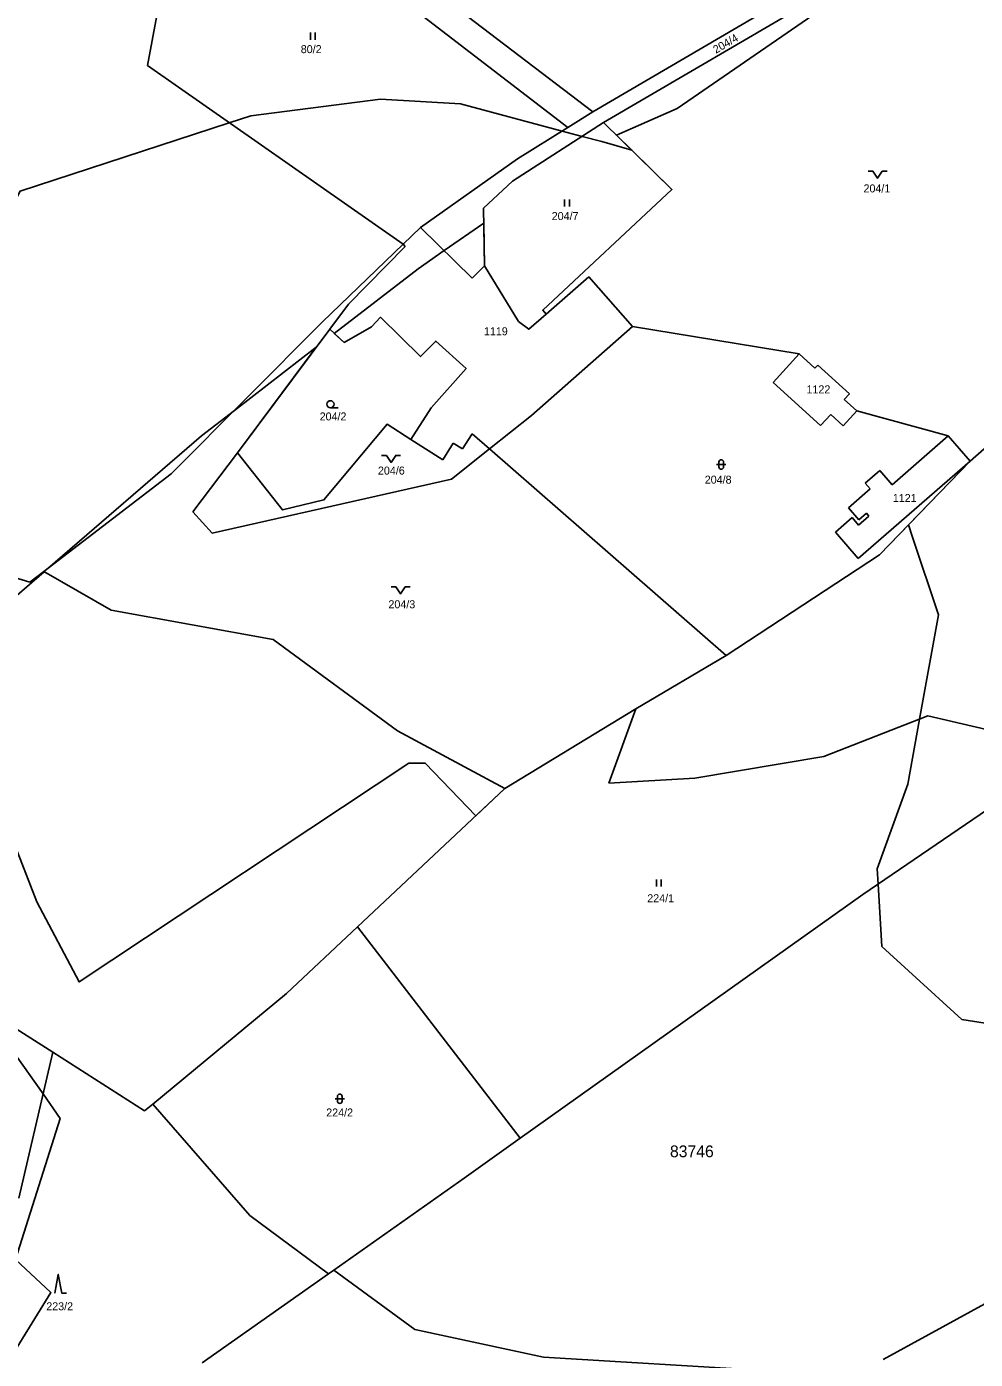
# Model space of a CAD drawing. Extents: x -547623 to -538651, y -1096714 to -1086522.
# Drawn here: x -542226.1 to -542024.7, y -1091898.7 to -1091615.6 of the extents above; entities that cross this region are included whole.
import ezdxf

# ---------------------------------------------------------------- set-up
doc = ezdxf.new("R2010")
doc.units = 0
for name, color, linetype in [('Vrstva 1', 7, 'Continuous'), ('Vrstva 25', 7, 'Continuous'), ('Vrstva 52', 7, 'Continuous'), ('Vrstva 53', 7, 'Continuous'), ('Vrstva 86', 7, 'Continuous')]:
    doc.layers.add(name, color=color, linetype=linetype)

msp = doc.modelspace()

# ---------------------------------------------------------------- linework, layer by layer
at = {"layer": 'Vrstva 1'}
for points in [[(-542232.34, -1091537.35), (-542105.9, -1091633.69)], [(-542111.2, -1091637), (-542220.74, -1091552.82)], [(-542195.28, -1091596.05), (-542200.48, -1091623.86)], [(-542105.9, -1091633.69), (-542059.17, -1091606.26)], [(-542103.64, -1091635.97), (-542056.84, -1091608.54)], [(-542200.48, -1091623.86), (-542146.2, -1091661.82)], [(-542122.95, -1091648.39), (-542103.64, -1091635.97)], [(-542111.2, -1091637), (-542105.9, -1091633.69)], [(-542103.64, -1091635.97), (-542089.09, -1091650.19)], [(-542121.88, -1091643.68), (-542111.2, -1091637)], [(-542142.48, -1091658.23), (-542121.88, -1091643.68)], [(-542122.95, -1091648.39), (-542129.11, -1091654.13)], [(-542089.09, -1091650.19), (-542116.54, -1091675.79)], [(-542129.11, -1091654.13), (-542128.92, -1091666.36)], [(-542146.2, -1091661.82), (-542142.48, -1091658.23)], [(-542142.48, -1091658.23), (-542131.51, -1091669)], [(-542163.32, -1091678.3), (-542146.2, -1091661.82)], [(-542146.2, -1091661.82), (-542145.73, -1091662.28)], [(-542157.78, -1091674.55), (-542145.73, -1091662.28)], [(-542128.92, -1091666.36), (-542131.51, -1091669)], [(-542128.92, -1091666.36), (-542121.67, -1091678.18)], [(-542115.79, -1091676.64), (-542106.74, -1091668.71)], [(-542106.74, -1091668.71), (-542097.45, -1091679.3)], [(-542161.77, -1091679.87), (-542157.78, -1091674.55)], [(-542116.54, -1091675.79), (-542115.79, -1091676.64)], [(-542195.42, -1091710.59), (-542163.32, -1091678.3)], [(-542150.97, -1091677.32), (-542152.93, -1091679.32)], [(-542150.97, -1091677.32), (-542142.48, -1091685.66)], [(-542121.67, -1091678.18), (-542119.46, -1091679.86)], [(-542119.46, -1091679.86), (-542115.79, -1091676.64)], [(-542181.4, -1091706.09), (-542161.77, -1091679.87)], [(-542158.71, -1091682.65), (-542161.77, -1091679.87)], [(-542152.93, -1091679.32), (-542158.71, -1091682.65)], [(-542097.45, -1091679.3), (-542118.96, -1091698.16)], [(-542097.45, -1091679.3), (-542062.05, -1091685.09)], [(-541994.45, -1091680.31), (-542025.78, -1091707.87)], [(-542142.48, -1091685.66), (-542139.25, -1091682.37)], [(-542139.25, -1091682.37), (-542132.81, -1091688.18)], [(-542067.58, -1091691.14), (-542062.05, -1091685.09)], [(-542062.05, -1091685.09), (-542058.73, -1091688.13)], [(-542132.81, -1091688.18), (-542140.22, -1091696.53)], [(-542058.73, -1091688.13), (-542058.12, -1091687.46)], [(-542058.12, -1091687.46), (-542051.41, -1091693.61)], [(-542057.55, -1091700.32), (-542067.58, -1091691.14)], [(-542052.49, -1091694.79), (-542051.41, -1091693.61)], [(-542052.49, -1091694.79), (-542049.83, -1091697.22)], [(-542140.22, -1091696.53), (-542144.53, -1091703.27)], [(-542118.96, -1091698.16), (-542127.87, -1091705.29)], [(-542057.55, -1091700.32), (-542055.39, -1091697.96)], [(-542052.73, -1091700.39), (-542055.39, -1091697.96)], [(-542052.73, -1091700.39), (-542049.83, -1091697.22)], [(-542049.83, -1091697.22), (-542030.44, -1091702.52)], [(-542163.03, -1091716.13), (-542149.59, -1091700.04)], [(-542149.59, -1091700.04), (-542144.53, -1091703.27)], [(-542137.79, -1091707.58), (-542144.53, -1091703.27)], [(-542137.79, -1091707.58), (-542135.53, -1091704.04)], [(-542135.53, -1091704.04), (-542133.59, -1091705.28)], [(-542133.59, -1091705.28), (-542131.54, -1091702.08)], [(-542131.54, -1091702.08), (-542127.87, -1091705.29)], [(-542030.44, -1091702.52), (-542042.35, -1091712.89)], [(-542030.44, -1091702.52), (-542025.78, -1091707.87)], [(-542190.82, -1091718.67), (-542181.4, -1091706.09)], [(-542181.4, -1091706.09), (-542171.82, -1091718.24)], [(-542127.87, -1091705.29), (-542135.92, -1091711.73)], [(-542127.87, -1091705.29), (-542077.6, -1091749.14)], [(-542025.78, -1091707.87), (-542049.53, -1091728.55)], [(-542044.98, -1091709.87), (-542048.07, -1091712.56)], [(-542045, -1091727.75), (-542025.78, -1091707.87)], [(-542044.98, -1091709.87), (-542042.35, -1091712.89)], [(-542222.5, -1091731.35), (-542195.42, -1091710.59)], [(-542186.74, -1091723.15), (-542135.92, -1091711.73)], [(-542048.07, -1091712.56), (-542047.02, -1091713.77)], [(-542288.55, -1091714.43), (-542225.46, -1091733.62)], [(-542047.02, -1091713.77), (-542051.62, -1091717.77)], [(-542171.82, -1091718.24), (-542163.03, -1091716.13)], [(-542051.62, -1091717.77), (-542049.39, -1091720.34)], [(-542190.82, -1091718.67), (-542186.74, -1091723.15)], [(-542054.39, -1091722.97), (-542050.84, -1091719.88)], [(-542050.84, -1091719.88), (-542049.47, -1091721.47)], [(-542047.28, -1091719.56), (-542049.47, -1091721.47)], [(-542049.39, -1091720.34), (-542047.8, -1091718.96)], [(-542047.8, -1091718.96), (-542047.28, -1091719.56)], [(-542054.39, -1091722.97), (-542049.53, -1091728.55)], [(-542077.6, -1091749.14), (-542045, -1091727.75)], [(-542225.46, -1091733.62), (-542222.5, -1091731.35)], [(-542208.21, -1091739.5), (-542222.5, -1091731.35)], [(-542173.78, -1091745.78), (-542208.21, -1091739.5)], [(-542147.38, -1091765.19), (-542173.78, -1091745.78)], [(-542096.79, -1091760.5), (-542077.6, -1091749.14)], [(-542124.62, -1091777.44), (-542096.79, -1091760.5)], [(-542102.47, -1091776.26), (-542096.79, -1091760.5)], [(-542034.72, -1091761.97), (-542056.84, -1091770.59)], [(-542022.29, -1091764.85), (-542034.72, -1091761.97)], [(-542124.62, -1091777.44), (-542147.38, -1091765.19)], [(-542056.84, -1091770.59), (-542084.27, -1091775.22)], [(-542048.58, -1091799.95), (-542011.16, -1091774.42)], [(-542155.9, -1091806.83), (-542124.62, -1091777.44)], [(-542084.27, -1091775.22), (-542102.47, -1091776.26)], [(-542121.31, -1091851.72), (-542048.58, -1091799.95)], [(-542170.95, -1091820.98), (-542155.9, -1091806.83)], [(-542155.9, -1091806.83), (-542121.31, -1091851.72)], [(-542199.38, -1091844.47), (-542170.95, -1091820.98)], [(-542229.17, -1091827.94), (-542220.59, -1091833.44)], [(-542227.83, -1091864.42), (-542220.59, -1091833.44)], [(-542220.59, -1091833.44), (-542201.13, -1091845.92)], [(-542201.13, -1091845.92), (-542199.38, -1091844.47)], [(-542199.38, -1091844.47), (-542178.75, -1091868.1)], [(-542133.23, -1091860.2), (-542121.31, -1091851.72)], [(-542160.92, -1091879.72), (-542133.23, -1091860.2)], [(-542044.21, -1091898.74), (-541981.66, -1091864.43)], [(-542178.75, -1091868.1), (-542162.04, -1091880.51)], [(-542162.04, -1091880.51), (-542160.92, -1091879.72)], [(-542160.92, -1091879.72), (-542143.69, -1091892.32)], [(-542188.88, -1091899.43), (-542162.04, -1091880.51)], [(-542143.69, -1091892.32), (-542116.39, -1091898.18)], [(-542116.39, -1091898.18), (-542069.46, -1091901.06)]]:
    msp.add_lwpolyline(points, dxfattribs=at)
at = {"layer": 'Vrstva 25'}
for p, q in [((-542165.89, -1091618.35), (-542165.89, -1091616.85)), ((-542164.89, -1091618.35), (-542164.89, -1091616.85)), ((-542111.89, -1091653.77), (-542111.89, -1091652.27)), ((-542110.89, -1091653.77), (-542110.89, -1091652.27)), ((-542161.62, -1091696.53), (-542160.02, -1091696.53)), ((-542079.62, -1091708.59), (-542077.62, -1091708.59)), ((-542079.12, -1091709.09), (-542079.12, -1091708.09)), ((-542078.12, -1091708.09), (-542078.12, -1091709.09)), ((-542092.4, -1091798.24), (-542092.4, -1091796.74)), ((-542091.4, -1091798.24), (-542091.4, -1091796.74)), ((-542160.15, -1091843.82), (-542160.15, -1091842.82)), ((-542159.15, -1091842.82), (-542159.15, -1091843.82)), ((-542160.65, -1091843.32), (-542158.65, -1091843.32))]:
    msp.add_line(p, q, dxfattribs=at)
for points in [[(-542047.42, -1091646.28), (-542046.42, -1091646.28), (-542045.42, -1091647.78), (-542044.42, -1091646.28), (-542043.42, -1091646.28)], [(-542150.75, -1091706.66), (-542149.75, -1091706.66), (-542148.75, -1091708.16), (-542147.75, -1091706.66), (-542146.75, -1091706.66)], [(-542148.73, -1091734.59), (-542147.73, -1091734.59), (-542146.73, -1091736.09), (-542145.73, -1091734.59), (-542144.73, -1091734.59)], [(-542220.15, -1091884.62), (-542219.45, -1091880.62), (-542218.65, -1091884.62), (-542217.65, -1091884.62)]]:
    msp.add_lwpolyline(points, dxfattribs=at)
msp.add_circle((-542161.62, -1091695.78), 0.75, dxfattribs=at)
for centre, start, end in [((-542078.62, -1091708.09), 0, 180), ((-542078.62, -1091709.09), 180, 0), ((-542159.65, -1091842.82), 0, 180), ((-542159.65, -1091843.82), 180, 0)]:
    msp.add_arc(centre, 0.5, start, end, dxfattribs=at)
at = {"layer": 'Vrstva 52'}
for points in [[(-542097.63, -1091641.85), (-542104, -1091640), (-542108.17, -1091638.89), (-542112.41, -1091637.76), (-542134, -1091632), (-542151, -1091631), (-542178.5, -1091634.5), (-542183.11, -1091636.01), (-542227.5, -1091650.5), (-542234, -1091662.5), (-542231, -1091679), (-542228.5, -1091703), (-542233, -1091712), (-542239, -1091718), (-542248, -1091719), (-542262.5, -1091712), (-542270.5, -1091694), (-542268, -1091669.5), (-542229.5, -1091595), (-542223.92, -1091573.85), (-542218.77, -1091554.33), (-542217.31, -1091548.8), (-542208, -1091513.5)], [(-542097.63, -1091641.85), (-542100.9, -1091638.64), (-542088, -1091633), (-542031.5, -1091594), (-542022, -1091591), (-541994.5, -1091678)], [(-542038.87, -1091721.41), (-542045, -1091727.75), (-542077.6, -1091749.14), (-542096.79, -1091760.5), (-542124.62, -1091777.44), (-542130.74, -1091783.19), (-542141.5, -1091772), (-542145, -1091772), (-542215, -1091818.5), (-542224, -1091801.5), (-542244, -1091750), (-542222.44, -1091731.38), (-542221.66, -1091730.7), (-542189, -1091702.5), (-542182.03, -1091697.12), (-542164.63, -1091683.7), (-542181.4, -1091706.09), (-542171.82, -1091718.24), (-542163.03, -1091716.13), (-542149.59, -1091700.04), (-542144.53, -1091703.27), (-542140.22, -1091696.53), (-542132.81, -1091688.18), (-542139.25, -1091682.37), (-542142.48, -1091685.66), (-542150.97, -1091677.32), (-542152.93, -1091679.32), (-542158.71, -1091682.65), (-542160.81, -1091680.74), (-542143, -1091667), (-542137.46, -1091663.16), (-542129.06, -1091657.35), (-542128.92, -1091666.36), (-542121.67, -1091678.18), (-542119.46, -1091679.86), (-542115.79, -1091676.64), (-542116.54, -1091675.79), (-542089.09, -1091650.19), (-542097.63, -1091641.85)], [(-541994.5, -1091678), (-541996.22, -1091681.87), (-542007.27, -1091691.58), (-542012.5, -1091696), (-542013.36, -1091696.95), (-542025.78, -1091707.87), (-542038.87, -1091721.41)], [(-541947.5, -1091813), (-541991, -1091828), (-542005, -1091830), (-542027.5, -1091826.5), (-542044.5, -1091811), (-542045.31, -1091797.72), (-542045.5, -1091794.5), (-542039, -1091776.5), (-542036.5, -1091762.66), (-542032.5, -1091740.5), (-542038, -1091724), (-542038.87, -1091721.41)], [(-542306.53, -1091859.1), (-542304, -1091864), (-542228.5, -1091834), (-542222.66, -1091842.3), (-542219, -1091847.5), (-542228.5, -1091877.5), (-542221, -1091884.5), (-542240.5, -1091916), (-542255, -1091909), (-542274.29, -1091904.32), (-542283.58, -1091893.68), (-542290.62, -1091898.83)]]:
    msp.add_lwpolyline(points, dxfattribs=at)

# ---------------------------------------------------------------- texts
at = {"layer": 'Vrstva 53'}
msp.add_text('83746', height=2.5, dxfattribs=at).set_placement((-542089.52, -1091855.74))
at = {"layer": 'Vrstva 86'}
for s, p in [('80/2', (-542167.93, -1091621.21)), ('204/1', (-542048.41, -1091650.79)), ('204/7', (-542114.63, -1091656.66)), ('1119', (-542129.03, -1091681.14)), ('1122', (-542060.52, -1091693.48)), ('204/2', (-542163.92, -1091699.23)), ('204/6', (-542151.54, -1091710.73)), ('204/8', (-542082.13, -1091712.66)), ('1121', (-542042.19, -1091716.55)), ('204/3', (-542149.31, -1091739.13)), ('224/1', (-542094.34, -1091801.58)), ('224/2', (-542162.52, -1091847.09)), ('223/2', (-542221.98, -1091888.26))]:
    msp.add_text(s, height=1.7, dxfattribs=at).set_placement(p)
msp.add_text('204/4', height=1.7, rotation=30.4132, dxfattribs=at).set_placement((-542079.75, -1091621.35))

doc.saveas('drawing.dxf')
